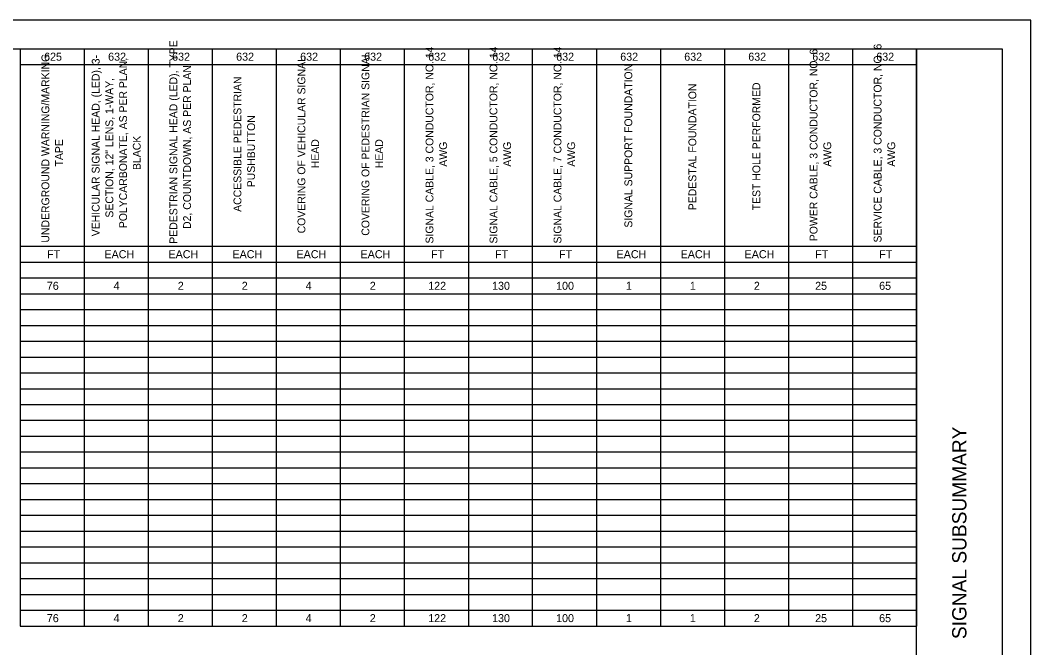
# Model space of a CAD drawing. Extents: x 0 to 34, y 0 to 22.
# Drawn here: x 16.33 to 34, y 11.03 to 22 of the extents above; entities that cross this region are included whole.
import ezdxf

# ---------------------------------------------------------------- set-up
doc = ezdxf.new("R2010")
doc.units = 0
for name, color, linetype in [('SH_Border', 7, 'Continuous'), ('SH_Cut_Line', 7, 'Continuous'), ('SH_Data', 7, 'Continuous')]:
    doc.layers.add(name, color=color, linetype=linetype)

msp = doc.modelspace()

# ---------------------------------------------------------------- linework, layer by layer
at = {"layer": 'SH_Border'}
msp.add_line((32, 0.5), (32, 21.5), dxfattribs=at)
msp.add_lwpolyline([(1.5, 21.5), (33.5, 21.5), (33.5, 0.5), (1.5, 0.5)], close=True, dxfattribs=at)
at = {"layer": 'SH_Cut_Line'}
msp.add_lwpolyline([(0, 0), (34, 0), (34, 22), (0, 22)], close=True, dxfattribs=at)
at = {"layer": 'SH_Data'}
for p, q in [((16.325, 21.5), (23.043, 21.5)), ((16.325, 21.5), (16.325, 21.223)), ((17.445, 21.5), (17.445, 21.223)), ((18.565, 21.5), (18.565, 21.223)), ((19.684, 21.5), (19.684, 21.223)), ((20.804, 21.5), (20.804, 21.223)), ((21.923, 21.5), (21.923, 21.223)), ((23.043, 21.5), (24.163, 21.5)), ((23.043, 21.5), (23.043, 21.223)), ((24.163, 21.5), (25.282, 21.5)), ((24.163, 21.5), (24.163, 21.223)), ((25.282, 21.5), (28.641, 21.5)), ((25.282, 21.5), (25.282, 21.223)), ((26.402, 21.5), (26.402, 21.223)), ((27.522, 21.5), (27.522, 21.223)), ((28.641, 21.5), (29.761, 21.5)), ((28.641, 21.5), (28.641, 21.223)), ((29.761, 21.5), (30.88, 21.5)), ((29.761, 21.5), (29.761, 21.223)), ((30.88, 21.5), (32, 21.5)), ((30.88, 21.5), (30.88, 21.223)), ((32, 21.5), (32, 21.223)), ((16.325, 21.223), (23.043, 21.223)), ((16.325, 21.223), (16.325, 20.947)), ((17.445, 21.223), (17.445, 20.947)), ((18.565, 21.223), (18.565, 20.947)), ((19.684, 21.223), (19.684, 20.947)), ((20.804, 21.223), (20.804, 20.947)), ((21.923, 21.223), (21.923, 20.947)), ((23.043, 21.223), (24.163, 21.223)), ((23.043, 21.223), (23.043, 20.947)), ((24.163, 21.223), (25.282, 21.223)), ((24.163, 21.223), (24.163, 20.947)), ((25.282, 21.223), (28.641, 21.223)), ((25.282, 21.223), (25.282, 20.947)), ((26.402, 21.223), (26.402, 20.947)), ((27.522, 21.223), (27.522, 20.947)), ((28.641, 21.223), (29.761, 21.223)), ((28.641, 21.223), (28.641, 20.947)), ((29.761, 21.223), (30.88, 21.223)), ((29.761, 21.223), (29.761, 20.947)), ((30.88, 21.223), (32, 21.223)), ((30.88, 21.223), (30.88, 20.947)), ((32, 21.223), (32, 20.947)), ((16.325, 20.947), (16.325, 20.67)), ((17.445, 20.947), (17.445, 20.67)), ((18.565, 20.947), (18.565, 20.67)), ((19.684, 20.947), (19.684, 20.67)), ((20.804, 20.947), (20.804, 20.67)), ((21.923, 20.947), (21.923, 20.67)), ((23.043, 20.947), (23.043, 20.67)), ((24.163, 20.947), (24.163, 20.67)), ((25.282, 20.947), (25.282, 20.67)), ((26.402, 20.947), (26.402, 20.67)), ((27.522, 20.947), (27.522, 20.67)), ((28.641, 20.947), (28.641, 20.67)), ((29.761, 20.947), (29.761, 20.67)), ((30.88, 20.947), (30.88, 20.67)), ((32, 20.947), (32, 20.67)), ((16.325, 20.67), (16.325, 20.393)), ((17.445, 20.67), (17.445, 20.393)), ((18.565, 20.67), (18.565, 20.393)), ((19.684, 20.67), (19.684, 20.393)), ((20.804, 20.67), (20.804, 20.393)), ((21.923, 20.67), (21.923, 20.393)), ((23.043, 20.67), (23.043, 20.393)), ((24.163, 20.67), (24.163, 20.393)), ((25.282, 20.67), (25.282, 20.393)), ((26.402, 20.67), (26.402, 20.393)), ((27.522, 20.67), (27.522, 20.393)), ((28.641, 20.67), (28.641, 20.393)), ((29.761, 20.67), (29.761, 20.393)), ((30.88, 20.67), (30.88, 20.393)), ((32, 20.67), (32, 20.393)), ((16.325, 20.393), (16.325, 20.116)), ((17.445, 20.393), (17.445, 20.116)), ((18.565, 20.393), (18.565, 20.116)), ((19.684, 20.393), (19.684, 20.116)), ((20.804, 20.393), (20.804, 20.116)), ((21.923, 20.393), (21.923, 20.116)), ((23.043, 20.393), (23.043, 20.116)), ((24.163, 20.393), (24.163, 20.116)), ((25.282, 20.393), (25.282, 20.116)), ((26.402, 20.393), (26.402, 20.116)), ((27.522, 20.393), (27.522, 20.116)), ((28.641, 20.393), (28.641, 20.116)), ((29.761, 20.393), (29.761, 20.116)), ((30.88, 20.393), (30.88, 20.116)), ((32, 20.393), (32, 20.116)), ((16.325, 20.116), (16.325, 19.84)), ((17.445, 20.116), (17.445, 19.84)), ((18.565, 20.116), (18.565, 19.84)), ((19.684, 20.116), (19.684, 19.84)), ((20.804, 20.116), (20.804, 19.84)), ((21.923, 20.116), (21.923, 19.84)), ((23.043, 20.116), (23.043, 19.84)), ((24.163, 20.116), (24.163, 19.84)), ((25.282, 20.116), (25.282, 19.84)), ((26.402, 20.116), (26.402, 19.84)), ((27.522, 20.116), (27.522, 19.84)), ((28.641, 20.116), (28.641, 19.84)), ((29.761, 20.116), (29.761, 19.84)), ((30.88, 20.116), (30.88, 19.84)), ((32, 20.116), (32, 19.84)), ((16.325, 19.84), (16.325, 19.563)), ((17.445, 19.84), (17.445, 19.563)), ((18.565, 19.84), (18.565, 19.563)), ((19.684, 19.84), (19.684, 19.563)), ((20.804, 19.84), (20.804, 19.563)), ((21.923, 19.84), (21.923, 19.563)), ((23.043, 19.84), (23.043, 19.563)), ((24.163, 19.84), (24.163, 19.563)), ((25.282, 19.84), (25.282, 19.563)), ((26.402, 19.84), (26.402, 19.563)), ((27.522, 19.84), (27.522, 19.563)), ((28.641, 19.84), (28.641, 19.563)), ((29.761, 19.84), (29.761, 19.563)), ((30.88, 19.84), (30.88, 19.563)), ((32, 19.84), (32, 19.563)), ((16.325, 19.563), (16.325, 18.878)), ((17.445, 19.563), (17.445, 18.878)), ((18.565, 19.563), (18.565, 18.878)), ((19.684, 19.563), (19.684, 18.878)), ((20.804, 19.563), (20.804, 18.878)), ((21.923, 19.563), (21.923, 18.878)), ((23.043, 19.563), (23.043, 18.878)), ((24.163, 19.563), (24.163, 18.878)), ((25.282, 19.563), (25.282, 18.878)), ((26.402, 19.563), (26.402, 18.878)), ((27.522, 19.563), (27.522, 18.878)), ((28.641, 19.563), (28.641, 18.878)), ((29.761, 19.563), (29.761, 18.878)), ((30.88, 19.563), (30.88, 18.878)), ((32, 19.563), (32, 18.878)), ((16.325, 18.878), (16.325, 18.048)), ((17.445, 18.878), (17.445, 18.048)), ((18.565, 18.878), (18.565, 18.048)), ((19.684, 18.878), (19.684, 18.048)), ((20.804, 18.878), (20.804, 18.048)), ((21.923, 18.878), (21.923, 18.048)), ((23.043, 18.878), (23.043, 18.048)), ((24.163, 18.878), (24.163, 18.048)), ((25.282, 18.878), (25.282, 18.048)), ((26.402, 18.878), (26.402, 18.048)), ((27.522, 18.878), (27.522, 18.048)), ((28.641, 18.878), (28.641, 18.048)), ((29.761, 18.878), (29.761, 18.048)), ((30.88, 18.878), (30.88, 18.048)), ((32, 18.878), (32, 18.048)), ((16.325, 18.048), (23.043, 18.048)), ((16.325, 18.048), (16.325, 17.771)), ((17.445, 18.048), (17.445, 17.771)), ((18.565, 18.048), (18.565, 17.771)), ((19.684, 18.048), (19.684, 17.771)), ((20.804, 18.048), (20.804, 17.771)), ((21.923, 18.048), (21.923, 17.771)), ((23.043, 18.048), (24.163, 18.048)), ((23.043, 18.048), (23.043, 17.771)), ((24.163, 18.048), (25.282, 18.048)), ((24.163, 18.048), (24.163, 17.771)), ((25.282, 18.048), (28.641, 18.048)), ((25.282, 18.048), (25.282, 17.771)), ((26.402, 18.048), (26.402, 17.771)), ((27.522, 18.048), (27.522, 17.771)), ((28.641, 18.048), (29.761, 18.048)), ((28.641, 18.048), (28.641, 17.771)), ((29.761, 18.048), (30.88, 18.048)), ((29.761, 18.048), (29.761, 17.771)), ((30.88, 18.048), (32, 18.048)), ((30.88, 18.048), (30.88, 17.771)), ((32, 18.048), (32, 17.771)), ((16.325, 17.771), (23.043, 17.771)), ((16.325, 17.771), (16.325, 17.218)), ((17.445, 17.771), (17.445, 17.218)), ((18.565, 17.771), (18.565, 17.218)), ((19.684, 17.771), (19.684, 17.218)), ((20.804, 17.771), (20.804, 17.218)), ((21.923, 17.771), (21.923, 17.218)), ((23.043, 17.771), (24.163, 17.771)), ((23.043, 17.771), (23.043, 17.218)), ((24.163, 17.771), (25.282, 17.771)), ((24.163, 17.771), (24.163, 17.218)), ((25.282, 17.771), (28.641, 17.771)), ((25.282, 17.771), (25.282, 17.218)), ((26.402, 17.771), (26.402, 17.218)), ((27.522, 17.771), (27.522, 17.218)), ((28.641, 17.771), (29.761, 17.771)), ((28.641, 17.771), (28.641, 17.218)), ((29.761, 17.771), (30.88, 17.771)), ((29.761, 17.771), (29.761, 17.218)), ((30.88, 17.771), (32, 17.771)), ((30.88, 17.771), (30.88, 17.218)), ((32, 17.771), (32, 17.218)), ((16.325, 17.494), (23.043, 17.494)), ((23.043, 17.494), (24.163, 17.494)), ((24.163, 17.494), (25.282, 17.494)), ((25.282, 17.494), (28.641, 17.494)), ((28.641, 17.494), (29.761, 17.494)), ((29.761, 17.494), (30.88, 17.494)), ((30.88, 17.494), (32, 17.494)), ((16.325, 17.218), (23.043, 17.218)), ((16.325, 17.218), (16.325, 16.941)), ((17.445, 17.218), (17.445, 16.941)), ((18.565, 17.218), (18.565, 16.941)), ((19.684, 17.218), (19.684, 16.941)), ((20.804, 17.218), (20.804, 16.941)), ((21.923, 17.218), (21.923, 16.941)), ((23.043, 17.218), (24.163, 17.218)), ((23.043, 17.218), (23.043, 16.941)), ((24.163, 17.218), (25.282, 17.218)), ((24.163, 17.218), (24.163, 16.941)), ((25.282, 17.218), (28.641, 17.218)), ((25.282, 17.218), (25.282, 16.941)), ((26.402, 17.218), (26.402, 16.941)), ((27.522, 17.218), (27.522, 16.941)), ((28.641, 17.218), (29.761, 17.218)), ((28.641, 17.218), (28.641, 16.941)), ((29.761, 17.218), (30.88, 17.218)), ((29.761, 17.218), (29.761, 16.941)), ((30.88, 17.218), (32, 17.218)), ((30.88, 17.218), (30.88, 16.941)), ((32, 17.218), (32, 16.941)), ((16.325, 16.941), (23.043, 16.941)), ((16.325, 16.941), (16.325, 15.557)), ((17.445, 16.941), (17.445, 15.557)), ((18.565, 16.941), (18.565, 15.557)), ((19.684, 16.941), (19.684, 15.557)), ((20.804, 16.941), (20.804, 15.557)), ((21.923, 16.941), (21.923, 15.557)), ((23.043, 16.941), (24.163, 16.941)), ((23.043, 16.941), (23.043, 15.557)), ((24.163, 16.941), (25.282, 16.941)), ((24.163, 16.941), (24.163, 15.557)), ((25.282, 16.941), (28.641, 16.941)), ((25.282, 16.941), (25.282, 15.557)), ((26.402, 16.941), (26.402, 15.557)), ((27.522, 16.941), (27.522, 15.557)), ((28.641, 16.941), (29.761, 16.941)), ((28.641, 16.941), (28.641, 15.557)), ((29.761, 16.941), (30.88, 16.941)), ((29.761, 16.941), (29.761, 15.557)), ((30.88, 16.941), (32, 16.941)), ((30.88, 16.941), (30.88, 15.557)), ((32, 16.941), (32, 15.557)), ((16.325, 16.664), (23.043, 16.664)), ((23.043, 16.664), (24.163, 16.664)), ((24.163, 16.664), (25.282, 16.664)), ((25.282, 16.664), (28.641, 16.664)), ((28.641, 16.664), (29.761, 16.664)), ((29.761, 16.664), (30.88, 16.664)), ((30.88, 16.664), (32, 16.664)), ((16.325, 16.388), (23.043, 16.388)), ((23.043, 16.388), (24.163, 16.388)), ((24.163, 16.388), (25.282, 16.388)), ((25.282, 16.388), (28.641, 16.388)), ((28.641, 16.388), (29.761, 16.388)), ((29.761, 16.388), (30.88, 16.388)), ((30.88, 16.388), (32, 16.388)), ((16.325, 16.111), (23.043, 16.111)), ((23.043, 16.111), (24.163, 16.111)), ((24.163, 16.111), (25.282, 16.111)), ((25.282, 16.111), (28.641, 16.111)), ((28.641, 16.111), (29.761, 16.111)), ((29.761, 16.111), (30.88, 16.111)), ((30.88, 16.111), (32, 16.111)), ((16.325, 15.834), (23.043, 15.834)), ((23.043, 15.834), (24.163, 15.834)), ((24.163, 15.834), (25.282, 15.834)), ((25.282, 15.834), (28.641, 15.834)), ((28.641, 15.834), (29.761, 15.834)), ((29.761, 15.834), (30.88, 15.834)), ((30.88, 15.834), (32, 15.834)), ((16.325, 15.557), (23.043, 15.557)), ((16.325, 15.557), (16.325, 15.004)), ((17.445, 15.557), (17.445, 15.004)), ((18.565, 15.557), (18.565, 15.004)), ((19.684, 15.557), (19.684, 15.004)), ((20.804, 15.557), (20.804, 15.004)), ((21.923, 15.557), (21.923, 15.004)), ((23.043, 15.557), (24.163, 15.557)), ((23.043, 15.557), (23.043, 15.004)), ((24.163, 15.557), (25.282, 15.557)), ((24.163, 15.557), (24.163, 15.004)), ((25.282, 15.557), (28.641, 15.557)), ((25.282, 15.557), (25.282, 15.004)), ((26.402, 15.557), (26.402, 15.004)), ((27.522, 15.557), (27.522, 15.004)), ((28.641, 15.557), (29.761, 15.557)), ((28.641, 15.557), (28.641, 15.004)), ((29.761, 15.557), (30.88, 15.557)), ((29.761, 15.557), (29.761, 15.004)), ((30.88, 15.557), (32, 15.557)), ((30.88, 15.557), (30.88, 15.004)), ((32, 15.557), (32, 15.004)), ((16.325, 15.281), (23.043, 15.281)), ((23.043, 15.281), (24.163, 15.281)), ((24.163, 15.281), (25.282, 15.281)), ((25.282, 15.281), (28.641, 15.281)), ((28.641, 15.281), (29.761, 15.281)), ((29.761, 15.281), (30.88, 15.281)), ((30.88, 15.281), (32, 15.281)), ((16.325, 15.004), (23.043, 15.004)), ((16.325, 15.004), (16.325, 14.451)), ((17.445, 15.004), (17.445, 14.451)), ((18.565, 15.004), (18.565, 14.451)), ((19.684, 15.004), (19.684, 14.451)), ((20.804, 15.004), (20.804, 14.451)), ((21.923, 15.004), (21.923, 14.451)), ((23.043, 15.004), (24.163, 15.004)), ((23.043, 15.004), (23.043, 14.451)), ((24.163, 15.004), (25.282, 15.004)), ((24.163, 15.004), (24.163, 14.451)), ((25.282, 15.004), (28.641, 15.004)), ((25.282, 15.004), (25.282, 14.451)), ((26.402, 15.004), (26.402, 14.451)), ((27.522, 15.004), (27.522, 14.451)), ((28.641, 15.004), (29.761, 15.004)), ((28.641, 15.004), (28.641, 14.451)), ((29.761, 15.004), (30.88, 15.004)), ((29.761, 15.004), (29.761, 14.451)), ((30.88, 15.004), (32, 15.004)), ((30.88, 15.004), (30.88, 14.451)), ((32, 15.004), (32, 14.451)), ((16.325, 14.727), (23.043, 14.727)), ((23.043, 14.727), (24.163, 14.727)), ((24.163, 14.727), (25.282, 14.727)), ((25.282, 14.727), (28.641, 14.727)), ((28.641, 14.727), (29.761, 14.727)), ((29.761, 14.727), (30.88, 14.727)), ((30.88, 14.727), (32, 14.727)), ((16.325, 14.451), (23.043, 14.451)), ((16.325, 14.451), (16.325, 14.174)), ((17.445, 14.451), (17.445, 14.174)), ((18.565, 14.451), (18.565, 14.174)), ((19.684, 14.451), (19.684, 14.174)), ((20.804, 14.451), (20.804, 14.174)), ((21.923, 14.451), (21.923, 14.174)), ((23.043, 14.451), (24.163, 14.451)), ((23.043, 14.451), (23.043, 14.174)), ((24.163, 14.451), (25.282, 14.451)), ((24.163, 14.451), (24.163, 14.174)), ((25.282, 14.451), (28.641, 14.451)), ((25.282, 14.451), (25.282, 14.174)), ((26.402, 14.451), (26.402, 14.174)), ((27.522, 14.451), (27.522, 14.174)), ((28.641, 14.451), (29.761, 14.451)), ((28.641, 14.451), (28.641, 14.174)), ((29.761, 14.451), (30.88, 14.451)), ((29.761, 14.451), (29.761, 14.174)), ((30.88, 14.451), (32, 14.451)), ((30.88, 14.451), (30.88, 14.174)), ((32, 14.451), (32, 14.174)), ((16.325, 14.174), (23.043, 14.174)), ((16.325, 14.174), (16.325, 13.62)), ((17.445, 14.174), (17.445, 13.62)), ((18.565, 14.174), (18.565, 13.62)), ((19.684, 14.174), (19.684, 13.62)), ((20.804, 14.174), (20.804, 13.62)), ((21.923, 14.174), (21.923, 13.62)), ((23.043, 14.174), (24.163, 14.174)), ((23.043, 14.174), (23.043, 13.62)), ((24.163, 14.174), (25.282, 14.174)), ((24.163, 14.174), (24.163, 13.62)), ((25.282, 14.174), (28.641, 14.174)), ((25.282, 14.174), (25.282, 13.62)), ((26.402, 14.174), (26.402, 13.62)), ((27.522, 14.174), (27.522, 13.62)), ((28.641, 14.174), (29.761, 14.174)), ((28.641, 14.174), (28.641, 13.62)), ((29.761, 14.174), (30.88, 14.174)), ((29.761, 14.174), (29.761, 13.62)), ((30.88, 14.174), (32, 14.174)), ((30.88, 14.174), (30.88, 13.62)), ((32, 14.174), (32, 13.62)), ((16.325, 13.897), (23.043, 13.897)), ((23.043, 13.897), (24.163, 13.897)), ((24.163, 13.897), (25.282, 13.897)), ((25.282, 13.897), (28.641, 13.897)), ((28.641, 13.897), (29.761, 13.897)), ((29.761, 13.897), (30.88, 13.897)), ((30.88, 13.897), (32, 13.897)), ((16.325, 13.62), (23.043, 13.62)), ((16.325, 13.62), (16.325, 13.344)), ((17.445, 13.62), (17.445, 13.344)), ((18.565, 13.62), (18.565, 13.344)), ((19.684, 13.62), (19.684, 13.344)), ((20.804, 13.62), (20.804, 13.344)), ((21.923, 13.62), (21.923, 13.344)), ((23.043, 13.62), (24.163, 13.62)), ((23.043, 13.62), (23.043, 13.344)), ((24.163, 13.62), (25.282, 13.62)), ((24.163, 13.62), (24.163, 13.344)), ((25.282, 13.62), (28.641, 13.62)), ((25.282, 13.62), (25.282, 13.344)), ((26.402, 13.62), (26.402, 13.344)), ((27.522, 13.62), (27.522, 13.344)), ((28.641, 13.62), (29.761, 13.62)), ((28.641, 13.62), (28.641, 13.344)), ((29.761, 13.62), (30.88, 13.62)), ((29.761, 13.62), (29.761, 13.344)), ((30.88, 13.62), (32, 13.62)), ((30.88, 13.62), (30.88, 13.344)), ((32, 13.62), (32, 13.344)), ((16.325, 13.344), (23.043, 13.344)), ((16.325, 13.344), (16.325, 12.514)), ((17.445, 13.344), (17.445, 12.514)), ((18.565, 13.344), (18.565, 12.514)), ((19.684, 13.344), (19.684, 12.514)), ((20.804, 13.344), (20.804, 12.514)), ((21.923, 13.344), (21.923, 12.514)), ((23.043, 13.344), (24.163, 13.344)), ((23.043, 13.344), (23.043, 12.514)), ((24.163, 13.344), (25.282, 13.344)), ((24.163, 13.344), (24.163, 12.514)), ((25.282, 13.344), (28.641, 13.344)), ((25.282, 13.344), (25.282, 12.514)), ((26.402, 13.344), (26.402, 12.514)), ((27.522, 13.344), (27.522, 12.514)), ((28.641, 13.344), (29.761, 13.344)), ((28.641, 13.344), (28.641, 12.514)), ((29.761, 13.344), (30.88, 13.344)), ((29.761, 13.344), (29.761, 12.514)), ((30.88, 13.344), (32, 13.344)), ((30.88, 13.344), (30.88, 12.514)), ((32, 13.344), (32, 12.514)), ((16.325, 13.067), (23.043, 13.067)), ((23.043, 13.067), (24.163, 13.067)), ((24.163, 13.067), (25.282, 13.067)), ((25.282, 13.067), (28.641, 13.067)), ((28.641, 13.067), (29.761, 13.067)), ((29.761, 13.067), (30.88, 13.067)), ((30.88, 13.067), (32, 13.067)), ((16.325, 12.79), (23.043, 12.79)), ((23.043, 12.79), (24.163, 12.79)), ((24.163, 12.79), (25.282, 12.79)), ((25.282, 12.79), (28.641, 12.79)), ((28.641, 12.79), (29.761, 12.79)), ((29.761, 12.79), (30.88, 12.79)), ((30.88, 12.79), (32, 12.79)), ((16.325, 12.514), (23.043, 12.514)), ((16.325, 12.514), (16.325, 11.96)), ((17.445, 12.514), (17.445, 11.96)), ((18.565, 12.514), (18.565, 11.96)), ((19.684, 12.514), (19.684, 11.96)), ((20.804, 12.514), (20.804, 11.96)), ((21.923, 12.514), (21.923, 11.96)), ((23.043, 12.514), (24.163, 12.514)), ((23.043, 12.514), (23.043, 11.96)), ((24.163, 12.514), (25.282, 12.514)), ((24.163, 12.514), (24.163, 11.96)), ((25.282, 12.514), (28.641, 12.514)), ((25.282, 12.514), (25.282, 11.96)), ((26.402, 12.514), (26.402, 11.96)), ((27.522, 12.514), (27.522, 11.96)), ((28.641, 12.514), (29.761, 12.514)), ((28.641, 12.514), (28.641, 11.96)), ((29.761, 12.514), (30.88, 12.514)), ((29.761, 12.514), (29.761, 11.96)), ((30.88, 12.514), (32, 12.514)), ((30.88, 12.514), (30.88, 11.96)), ((32, 12.514), (32, 11.96)), ((16.325, 12.237), (23.043, 12.237)), ((23.043, 12.237), (24.163, 12.237)), ((24.163, 12.237), (25.282, 12.237)), ((25.282, 12.237), (28.641, 12.237)), ((28.641, 12.237), (29.761, 12.237)), ((29.761, 12.237), (30.88, 12.237)), ((30.88, 12.237), (32, 12.237)), ((16.325, 11.96), (23.043, 11.96)), ((16.325, 11.96), (16.325, 11.407)), ((17.445, 11.96), (17.445, 11.407)), ((18.565, 11.96), (18.565, 11.407)), ((19.684, 11.96), (19.684, 11.407)), ((20.804, 11.96), (20.804, 11.407)), ((21.923, 11.96), (21.923, 11.407)), ((23.043, 11.96), (24.163, 11.96)), ((23.043, 11.96), (23.043, 11.407)), ((24.163, 11.96), (25.282, 11.96)), ((24.163, 11.96), (24.163, 11.407)), ((25.282, 11.96), (28.641, 11.96)), ((25.282, 11.96), (25.282, 11.407)), ((26.402, 11.96), (26.402, 11.407)), ((27.522, 11.96), (27.522, 11.407)), ((28.641, 11.96), (29.761, 11.96)), ((28.641, 11.96), (28.641, 11.407)), ((29.761, 11.96), (30.88, 11.96)), ((29.761, 11.96), (29.761, 11.407)), ((30.88, 11.96), (32, 11.96)), ((30.88, 11.96), (30.88, 11.407)), ((32, 11.96), (32, 11.407)), ((16.325, 11.684), (23.043, 11.684)), ((23.043, 11.684), (24.163, 11.684)), ((24.163, 11.684), (25.282, 11.684)), ((25.282, 11.684), (28.641, 11.684)), ((28.641, 11.684), (29.761, 11.684)), ((29.761, 11.684), (30.88, 11.684)), ((30.88, 11.684), (32, 11.684)), ((16.325, 11.407), (23.043, 11.407)), ((23.043, 11.407), (24.163, 11.407)), ((24.163, 11.407), (25.282, 11.407)), ((25.282, 11.407), (28.641, 11.407)), ((28.641, 11.407), (29.761, 11.407)), ((29.761, 11.407), (30.88, 11.407)), ((30.88, 11.407), (32, 11.407))]:
    msp.add_line(p, q, dxfattribs=at)

# ---------------------------------------------------------------- texts
for s, height, p in [('PEDESTRIAN SIGNAL HEAD (LED), TYPE ', 0.13674, (19.073, 18.092)), ('SERVICE CABLE, 3 CONDUCTOR, NO. 6 ', 0.13674, (31.389, 18.113)), ('UNDERGROUND WARNING/MARKING ', 0.13674, (16.834, 18.111)), ('COVERING OF PEDESTRIAN SIGNAL ', 0.13674, (22.432, 18.232)), ('SIGNAL CABLE, 3 CONDUCTOR, NO. 14 ', 0.13674, (23.552, 18.095)), ('SIGNAL CABLE, 5 CONDUCTOR, NO. 14 ', 0.13674, (24.671, 18.095)), ('SIGNAL CABLE, 7 CONDUCTOR, NO. 14 ', 0.13674, (25.791, 18.095)), ('POWER CABLE, 3 CONDUCTOR, NO. 6 ', 0.13674, (30.269, 18.136)), ('VEHICULAR SIGNAL HEAD, (LED), 3-', 0.13674, (17.714, 18.222)), ('POLYCARBONATE, AS PER PLAN, ', 0.13674, (18.193, 18.364)), ('COVERING OF VEHICULAR SIGNAL ', 0.13674, (21.312, 18.273)), ('SIGNAL SUPPORT FOUNDATION', 0.13674, (27.03, 18.373)), ('D2, COUNTDOWN, AS PER PLAN', 0.13674, (19.312, 18.35)), ('SECTION, 12" LENS, 1-WAY, ', 0.13674, (17.953, 18.548)), ('ACCESSIBLE PEDESTRIAN ', 0.13674, (20.193, 18.649)), ('PEDESTAL FOUNDATION', 0.13674, (28.15, 18.678)), ('TEST HOLE PERFORMED', 0.13674, (29.269, 18.676)), ('PUSHBUTTON', 0.1367, (20.432, 19.079)), ('BLACK', 0.1367, (18.432, 19.381)), ('TAPE', 0.1367, (17.073, 19.443)), ('HEAD', 0.1367, (21.552, 19.412)), ('HEAD', 0.1367, (22.671, 19.412)), ('AWG', 0.1367, (23.791, 19.439)), ('AWG', 0.1367, (24.91, 19.439)), ('AWG', 0.1367, (26.03, 19.439)), ('AWG', 0.1367, (30.509, 19.439)), ('AWG', 0.1367, (31.628, 19.439)), ('SIGNAL SUBSUMMARY', 0.25, (32.875, 11.179))]:
    msp.add_text(s, height=height, rotation=90, dxfattribs=at).set_placement(p)
for s, p in [('625', (16.743, 21.292)), ('632', (17.863, 21.292)), ('632', (18.982, 21.292)), ('632', (20.102, 21.292)), ('632', (21.222, 21.292)), ('632', (22.341, 21.292)), ('632', (23.461, 21.292)), ('632', (24.581, 21.292)), ('632', (25.7, 21.292)), ('632', (26.82, 21.292)), ('632', (27.939, 21.292)), ('632', (29.059, 21.292)), ('632', (30.179, 21.292)), ('632', (31.298, 21.292)), ('FT', (16.794, 17.839)), ('EACH', (17.799, 17.839)), ('EACH', (18.919, 17.839)), ('EACH', (20.038, 17.839)), ('EACH', (21.158, 17.839)), ('EACH', (22.278, 17.839)), ('FT', (23.512, 17.839)), ('FT', (24.631, 17.839)), ('FT', (25.751, 17.839)), ('EACH', (26.756, 17.839)), ('EACH', (27.876, 17.839)), ('EACH', (28.995, 17.839)), ('FT', (30.23, 17.839)), ('FT', (31.349, 17.839)), ('76', (16.791, 17.286)), ('4', (17.958, 17.286)), ('2', (19.081, 17.286)), ('2', (20.2, 17.286)), ('4', (21.317, 17.286)), ('2', (22.439, 17.286)), ('122', (23.461, 17.286)), ('130', (24.578, 17.286)), ('100', (25.698, 17.286)), ('1', (26.918, 17.286)), ('1', (28.037, 17.286)), ('2', (29.157, 17.286)), ('25', (30.228, 17.286)), ('65', (31.348, 17.286)), ('76', (16.791, 11.475)), ('4', (17.958, 11.475)), ('2', (19.081, 11.475)), ('2', (20.2, 11.475)), ('4', (21.317, 11.475)), ('2', (22.439, 11.475)), ('122', (23.461, 11.475)), ('130', (24.578, 11.475)), ('100', (25.698, 11.475)), ('1', (26.918, 11.475)), ('1', (28.037, 11.475)), ('2', (29.157, 11.475)), ('25', (30.228, 11.475)), ('65', (31.348, 11.475))]:
    msp.add_text(s, height=0.14, dxfattribs=at).set_placement(p)

doc.saveas('drawing.dxf')
